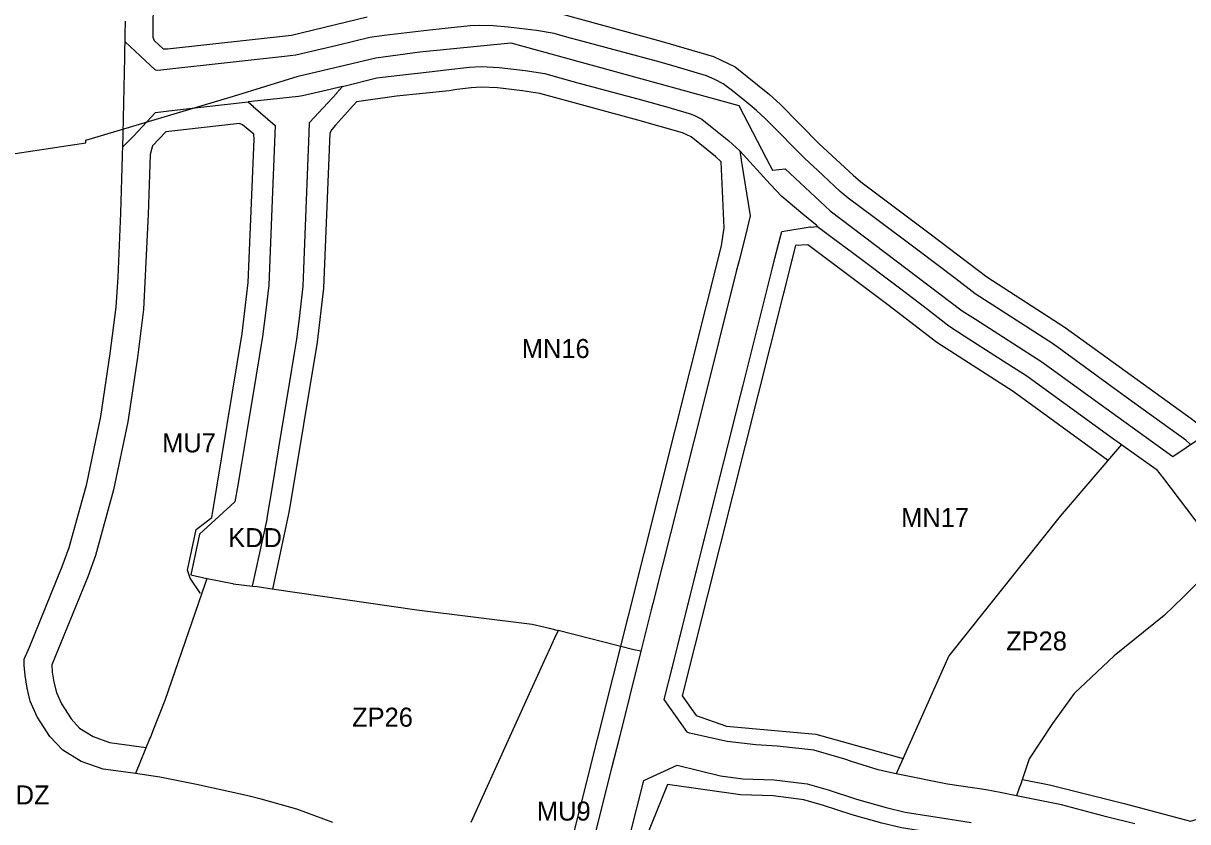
# Model space of a CAD drawing. Extents: x 7428103 to 7431580, y 5545880 to 5549002.
# Drawn here: x 7430217.3 to 7430556.7, y 5547582.8 to 5547815.6 of the extents above; entities that cross this region are included whole.
import ezdxf

# ---------------------------------------------------------------- set-up
doc = ezdxf.new("R2010")
doc.units = 0
for name, color, linetype in [('CZ_L_linie rozgraniczające tereny o różnym przeznaczeniu oraz różnych warunkach ich zabudowy i zagospodarowania', 7, 'Continuous'), ('CZ_L_maksymalne nieprzekraczalne linie zabudowy', 7, 'Continuous'), ('CZ_L_opisy_linie rozgraniczające tereny o różnym przeznaczeniu oraz różnych warunkach ich zabudowy i zagospodarowania', 7, 'Continuous'), ('Łąki_Nowohuckie', 7, 'Continuous')]:
    doc.layers.add(name, color=color, linetype=linetype)

msp = doc.modelspace()

# ---------------------------------------------------------------- linework, layer by layer
at = {"layer": 'CZ_L_linie rozgraniczające tereny o różnym przeznaczeniu oraz różnych warunkach ich zabudowy i zagospodarowania'}
for p, q in [((7430247, 5547812.36), (7430247.08, 5547816.27)), ((7430334.03, 5547813.4), (7430322.49, 5547812.07)), ((7430341.14, 5547814.21), (7430334.03, 5547813.4)), ((7430347.51, 5547814.87), (7430341.14, 5547814.21)), ((7430350.39, 5547815.02), (7430347.51, 5547814.87)), ((7430354.22, 5547814.91), (7430350.39, 5547815.02)), ((7430358.61, 5547814.55), (7430354.22, 5547814.91)), ((7430366.92, 5547813.53), (7430358.61, 5547814.55)), ((7430372.07, 5547812.71), (7430366.92, 5547813.53)), ((7430375.37, 5547811.73), (7430372.07, 5547812.71)), ((7430246.91, 5547807.98), (7430246.95, 5547810.2)), ((7430246.95, 5547810.2), (7430247, 5547812.36)), ((7430251.35, 5547806.18), (7430246.95, 5547810.2)), ((7430318.27, 5547811.53), (7430308.81, 5547809.19)), ((7430322.49, 5547812.07), (7430318.27, 5547811.53)), ((7430380.49, 5547810.32), (7430375.37, 5547811.73)), ((7430390.95, 5547807.51), (7430380.49, 5547810.32)), ((7430246.86, 5547805.74), (7430246.91, 5547807.98)), ((7430255.84, 5547802.01), (7430251.35, 5547806.18)), ((7430293.44, 5547805.94), (7430279.35, 5547804.37)), ((7430296.73, 5547806.32), (7430293.44, 5547805.94)), ((7430308.81, 5547809.19), (7430296.73, 5547806.32)), ((7430401.9, 5547804.57), (7430390.95, 5547807.51)), ((7430246.36, 5547783.41), (7430246.86, 5547805.74)), ((7430279.35, 5547804.37), (7430256.5, 5547801.84)), ((7430340.44, 5547802.05), (7430347.34, 5547802.8)), ((7430347.34, 5547802.8), (7430350.73, 5547803.01)), ((7430350.73, 5547803.01), (7430355.97, 5547802.78)), ((7430355.97, 5547802.78), (7430363.61, 5547801.89)), ((7430407, 5547803.12), (7430401.9, 5547804.57)), ((7430412.88, 5547801.41), (7430407, 5547803.12)), ((7430256.5, 5547801.84), (7430255.84, 5547802.01)), ((7430310.33, 5547797.22), (7430320.37, 5547799.69)), ((7430320.37, 5547799.69), (7430321.98, 5547799.93)), ((7430321.98, 5547799.93), (7430327, 5547800.51)), ((7430327, 5547800.51), (7430336.43, 5547801.59)), ((7430336.43, 5547801.59), (7430340.44, 5547802.05)), ((7430363.61, 5547801.89), (7430369.32, 5547801)), ((7430369.32, 5547801), (7430373.04, 5547799.9)), ((7430373.04, 5547799.9), (7430378.89, 5547798.32)), ((7430416.45, 5547800.32), (7430412.88, 5547801.41)), ((7430418.83, 5547799.21), (7430416.45, 5547800.32)), ((7430421.31, 5547798.01), (7430418.83, 5547799.21)), ((7430306.72, 5547796.36), (7430298.69, 5547794.47)), ((7430310.33, 5547797.22), (7430306.72, 5547796.36)), ((7430308.6, 5547795.27), (7430310.33, 5547797.22)), ((7430378.89, 5547798.32), (7430389.78, 5547795.4)), ((7430423.98, 5547795.93), (7430421.31, 5547798.01)), ((7430429.17, 5547791.75), (7430423.98, 5547795.93)), ((7430269.91, 5547791.25), (7430282.86, 5547792.69)), ((7430289.35, 5547793.41), (7430282.86, 5547792.69)), ((7430282.86, 5547792.69), (7430284.34, 5547791.35)), ((7430297.46, 5547794.32), (7430289.35, 5547793.41)), ((7430298.69, 5547794.47), (7430297.46, 5547794.32)), ((7430300.75, 5547786.71), (7430308.65, 5547795.28)), ((7430308.65, 5547795.28), (7430308.6, 5547795.27)), ((7430389.78, 5547795.4), (7430396.41, 5547793.62)), ((7430396.41, 5547793.62), (7430405.15, 5547791.16)), ((7430249.37, 5547782.72), (7430255.8, 5547789.6)), ((7430255.8, 5547789.6), (7430259.69, 5547790.11)), ((7430259.69, 5547790.11), (7430269.91, 5547791.25)), ((7430284.34, 5547791.35), (7430284.29, 5547791.34)), ((7430284.29, 5547791.34), (7430290.72, 5547785.81)), ((7430405.15, 5547791.16), (7430411.38, 5547789.35)), ((7430411.38, 5547789.35), (7430412.73, 5547788.81)), ((7430431.05, 5547790.24), (7430429.17, 5547791.75)), ((7430433.66, 5547787.78), (7430431.05, 5547790.24)), ((7430290.72, 5547785.81), (7430289.66, 5547759.2)), ((7430300.64, 5547783.67), (7430300.75, 5547786.71)), ((7430412.73, 5547788.81), (7430415.06, 5547787.7)), ((7430415.06, 5547787.7), (7430418.12, 5547785.24)), ((7430436.96, 5547784.44), (7430433.66, 5547787.78)), ((7430246.28, 5547779.62), (7430246.36, 5547783.41)), ((7430246.28, 5547779.62), (7430249.37, 5547782.72)), ((7430299.85, 5547763.91), (7430300.64, 5547783.67)), ((7430418.12, 5547785.24), (7430422.92, 5547781.38)), ((7430442.56, 5547778.77), (7430436.96, 5547784.44)), ((7430246.23, 5547777.58), (7430246.28, 5547779.62)), ((7430422.92, 5547781.38), (7430426.12, 5547778.41)), ((7430445.14, 5547776.19), (7430442.56, 5547778.77)), ((7430245.68, 5547760.22), (7430246.22, 5547777.02)), ((7430246.22, 5547777.02), (7430246.23, 5547777.58)), ((7430435, 5547768.74), (7430426.12, 5547778.41)), ((7430426.12, 5547778.41), (7430426.57, 5547775.78)), ((7430426.57, 5547775.78), (7430426.6, 5547775.74)), ((7430426.6, 5547775.74), (7430429.22, 5547759.52)), ((7430448.8, 5547772.78), (7430445.14, 5547776.19)), ((7430455.42, 5547766.6), (7430448.8, 5547772.78)), ((7430438.4, 5547765.1), (7430435, 5547768.74)), ((7430444.5, 5547760), (7430438.4, 5547765.1)), ((7430457.79, 5547764.62), (7430455.42, 5547766.6)), ((7430298.96, 5547741.46), (7430299.85, 5547763.91)), ((7430465.3, 5547759), (7430457.79, 5547764.62)), ((7430244.88, 5547741.63), (7430245.68, 5547760.22)), ((7430289.66, 5547759.2), (7430288.82, 5547739.24)), ((7430429.22, 5547759.52), (7430427.68, 5547753.39)), ((7430448.66, 5547756.53), (7430444.5, 5547760)), ((7430478.06, 5547749.46), (7430465.3, 5547759)), ((7430437.91, 5547753.06), (7430438.37, 5547754.91)), ((7430438.37, 5547754.91), (7430446.66, 5547756.25)), ((7430446.66, 5547756.25), (7430446.75, 5547756.18)), ((7430446.75, 5547756.18), (7430448.66, 5547756.39)), ((7430448.66, 5547756.39), (7430448.66, 5547756.53)), ((7430448.66, 5547756.39), (7430448.82, 5547756.4)), ((7430448.82, 5547756.4), (7430452.31, 5547753.71)), ((7430427.68, 5547753.39), (7430425.94, 5547746.46)), ((7430436.41, 5547747.1), (7430437.91, 5547753.06)), ((7430452.31, 5547753.71), (7430453.45, 5547752.88)), ((7430453.45, 5547752.88), (7430459.36, 5547748.46)), ((7430459.36, 5547748.46), (7430472.67, 5547738.51)), ((7430489.09, 5547741.07), (7430478.06, 5547749.46)), ((7430425.94, 5547746.46), (7430425.14, 5547743.28)), ((7430435.62, 5547743.93), (7430436.41, 5547747.1)), ((7430244.37, 5547732.88), (7430244.88, 5547741.63)), ((7430298.85, 5547738.93), (7430298.96, 5547741.46)), ((7430425.14, 5547743.28), (7430415.05, 5547703)), ((7430427.12, 5547710.07), (7430435.62, 5547743.93)), ((7430288.82, 5547739.24), (7430287.98, 5547732.02)), ((7430297.75, 5547729.5), (7430298.85, 5547738.93)), ((7430472.67, 5547738.51), (7430480.84, 5547732.28)), ((7430494.74, 5547736.72), (7430489.09, 5547741.07)), ((7430503.96, 5547730.83), (7430494.74, 5547736.72)), ((7430242.63, 5547719.31), (7430244.37, 5547732.88)), ((7430287.95, 5547731.83), (7430287.04, 5547724.29)), ((7430287.98, 5547732.02), (7430287.93, 5547731.99)), ((7430287.93, 5547731.99), (7430287.95, 5547731.83)), ((7430480.84, 5547732.28), (7430487.1, 5547727.45)), ((7430297.05, 5547723.52), (7430297.75, 5547729.5)), ((7430508.12, 5547728.17), (7430503.96, 5547730.83)), ((7430517.58, 5547722.04), (7430508.12, 5547728.17)), ((7430487.1, 5547727.45), (7430491.55, 5547724.52)), ((7430491.55, 5547724.52), (7430502.97, 5547717.22)), ((7430287.04, 5547724.29), (7430285.17, 5547713.04)), ((7430296.47, 5547720.03), (7430297.05, 5547723.52)), ((7430533.18, 5547710.67), (7430517.58, 5547722.04)), ((7430239.87, 5547700.97), (7430242.63, 5547719.31)), ((7430294.79, 5547709.91), (7430296.47, 5547720.03)), ((7430502.97, 5547717.22), (7430509.82, 5547712.84)), ((7430285.16, 5547713), (7430282.44, 5547696.59)), ((7430285.19, 5547713.02), (7430285.16, 5547713)), ((7430285.17, 5547713.04), (7430285.19, 5547713.02)), ((7430509.82, 5547712.84), (7430515.61, 5547708.63)), ((7430292.38, 5547695.43), (7430294.79, 5547709.91)), ((7430426.37, 5547707.08), (7430427.12, 5547710.07)), ((7430515.61, 5547708.63), (7430526.51, 5547700.69)), ((7430540.66, 5547705.22), (7430533.18, 5547710.67)), ((7430416.66, 5547668.44), (7430426.37, 5547707.08)), ((7430554.16, 5547695.55), (7430540.66, 5547705.22)), ((7430235.8, 5547681.29), (7430239.87, 5547700.97)), ((7430415.05, 5547703), (7430403.62, 5547657.57)), ((7430526.51, 5547700.69), (7430534.45, 5547694.9)), ((7430282.44, 5547696.59), (7430280.89, 5547687.23)), ((7430290.08, 5547681.57), (7430292.38, 5547695.43)), ((7430534.45, 5547694.9), (7430537.42, 5547692.77)), ((7430556.18, 5547694.04), (7430554.16, 5547695.55)), ((7430557.44, 5547692.86), (7430556.18, 5547694.04)), ((7430537.42, 5547692.77), (7430519.55, 5547671.91)), ((7430537.42, 5547692.77), (7430547.49, 5547685.56)), ((7430280.89, 5547687.23), (7430279.85, 5547680.96)), ((7430547.49, 5547685.56), (7430549.72, 5547682.85)), ((7430230.6, 5547662.74), (7430235.8, 5547681.29)), ((7430279.85, 5547680.96), (7430278.97, 5547676.11)), ((7430288.39, 5547671.35), (7430290.08, 5547681.57)), ((7430549.72, 5547682.85), (7430560.99, 5547667.96)), ((7430278.97, 5547676.11), (7430268.6, 5547666.6)), ((7430284.13, 5547651.51), (7430288.32, 5547670.94)), ((7430288.32, 5547670.94), (7430288.39, 5547671.35)), ((7430519.55, 5547671.91), (7430487.09, 5547631.17)), ((7430413.27, 5547654.91), (7430416.66, 5547668.44)), ((7430268.6, 5547666.6), (7430266.12, 5547654.83)), ((7430228.65, 5547657.24), (7430230.6, 5547662.74)), ((7430219.05, 5547633.73), (7430228.65, 5547657.24)), ((7430403.62, 5547657.57), (7430400.83, 5547646.44)), ((7430266.12, 5547654.83), (7430270.81, 5547653.74)), ((7430270.81, 5547653.74), (7430270.32, 5547652.24)), ((7430270.81, 5547653.74), (7430270.84, 5547653.73)), ((7430270.84, 5547653.73), (7430274.38, 5547653.02)), ((7430406.49, 5547627.94), (7430413.27, 5547654.91)), ((7430270.32, 5547652.24), (7430258.56, 5547618.15)), ((7430274.38, 5547653.02), (7430275.39, 5547652.81)), ((7430275.39, 5547652.81), (7430278.31, 5547652.22)), ((7430278.31, 5547652.22), (7430278.37, 5547652.21)), ((7430278.37, 5547652.21), (7430278.41, 5547652.2)), ((7430278.41, 5547652.2), (7430284.13, 5547651.51)), ((7430284.13, 5547651.51), (7430285.45, 5547651.35)), ((7430285.45, 5547651.35), (7430290.4, 5547650.61)), ((7430290.4, 5547650.61), (7430331.98, 5547644.56)), ((7430400.83, 5547646.44), (7430400.35, 5547644.55)), ((7430331.98, 5547644.56), (7430365.59, 5547640.4)), ((7430400.35, 5547644.55), (7430397.33, 5547632.51)), ((7430365.59, 5547640.4), (7430369.02, 5547639.57)), ((7430369.02, 5547639.57), (7430370.58, 5547639.22)), ((7430370.58, 5547639.22), (7430373.19, 5547638.56)), ((7430372.17, 5547636.31), (7430370.87, 5547633.46)), ((7430373.19, 5547638.56), (7430372.17, 5547636.31)), ((7430395.27, 5547632.88), (7430373.19, 5547638.56)), ((7430217.57, 5547630.23), (7430219.05, 5547633.73)), ((7430370.87, 5547633.46), (7430369.65, 5547630.78)), ((7430397.33, 5547632.51), (7430395.27, 5547632.88)), ((7430217.54, 5547628.39), (7430217.57, 5547630.23)), ((7430369.65, 5547630.78), (7430364.28, 5547618.97)), ((7430397.33, 5547632.51), (7430393.98, 5547619.16)), ((7430487.09, 5547631.17), (7430471.73, 5547596.75)), ((7430217.78, 5547625.41), (7430217.54, 5547628.39)), ((7430404.11, 5547618.45), (7430406.49, 5547627.94)), ((7430218.39, 5547621.75), (7430217.78, 5547625.41)), ((7430219.29, 5547617.95), (7430218.39, 5547621.75)), ((7430393.98, 5547619.16), (7430390.84, 5547606.66)), ((7430221.36, 5547613.33), (7430219.29, 5547617.95)), ((7430258.56, 5547618.15), (7430255.06, 5547609.26)), ((7430364.28, 5547618.97), (7430355.34, 5547599.3)), ((7430410.71, 5547609.06), (7430404.11, 5547618.45)), ((7430224.96, 5547607.68), (7430221.36, 5547613.33)), ((7430255.06, 5547609.26), (7430254.65, 5547608.25)), ((7430410.85, 5547608.87), (7430410.71, 5547609.06)), ((7430228.76, 5547603.66), (7430224.96, 5547607.68)), ((7430254.2, 5547607.14), (7430249.99, 5547596.81)), ((7430254.42, 5547607.68), (7430254.2, 5547607.14)), ((7430254.65, 5547608.25), (7430254.42, 5547607.68)), ((7430390.84, 5547606.66), (7430388.75, 5547598.35)), ((7430411.52, 5547608.64), (7430410.85, 5547608.87)), ((7430422.47, 5547606.13), (7430411.52, 5547608.64)), ((7430430.83, 5547605.22), (7430422.47, 5547606.13)), ((7430234.14, 5547600.38), (7430228.76, 5547603.66)), ((7430437.03, 5547604.79), (7430430.83, 5547605.22)), ((7430445.12, 5547603.95), (7430437.03, 5547604.79)), ((7430447.74, 5547603.65), (7430445.12, 5547603.95)), ((7430454.49, 5547601.7), (7430447.74, 5547603.65)), ((7430240.56, 5547598.06), (7430234.14, 5547600.38)), ((7430355.34, 5547599.3), (7430347.7, 5547582.51)), ((7430398.17, 5547594.79), (7430407.93, 5547599.3)), ((7430407.93, 5547599.3), (7430420.48, 5547596.2)), ((7430456.81, 5547600.98), (7430454.49, 5547601.7)), ((7430458.69, 5547600.39), (7430456.81, 5547600.98)), ((7430466.49, 5547597.91), (7430458.69, 5547600.39)), ((7430247.21, 5547597.21), (7430240.56, 5547598.06)), ((7430249.99, 5547596.81), (7430247.21, 5547597.21)), ((7430257.06, 5547595.78), (7430249.99, 5547596.81)), ((7430267.77, 5547593.6), (7430257.06, 5547595.78)), ((7430388.75, 5547598.35), (7430381.91, 5547571.1)), ((7430420.48, 5547596.2), (7430427, 5547595.25)), ((7430468.99, 5547597.3), (7430466.49, 5547597.91)), ((7430471.73, 5547596.75), (7430468.99, 5547597.3)), ((7430486.75, 5547593.73), (7430471.73, 5547596.75)), ((7430282.31, 5547590.47), (7430267.77, 5547593.6)), ((7430394.32, 5547579.46), (7430398.17, 5547594.79)), ((7430427, 5547595.25), (7430436.18, 5547594.97)), ((7430436.18, 5547594.97), (7430441.77, 5547594.36)), ((7430441.77, 5547594.36), (7430445.77, 5547593.81)), ((7430445.77, 5547593.81), (7430451.94, 5547592.03)), ((7430451.94, 5547592.03), (7430460.16, 5547589.32)), ((7430497.98, 5547592.05), (7430486.75, 5547593.73)), ((7430502.09, 5547591.31), (7430497.98, 5547592.05)), ((7430286.62, 5547589.32), (7430282.31, 5547590.47)), ((7430296.98, 5547586.48), (7430286.62, 5547589.32)), ((7430460.16, 5547589.32), (7430468.79, 5547586.93)), ((7430506.85, 5547590.36), (7430502.09, 5547591.31)), ((7430519.96, 5547587.75), (7430506.85, 5547590.36)), ((7430307.53, 5547582.53), (7430296.98, 5547586.48)), ((7430468.79, 5547586.93), (7430474.35, 5547585.61)), ((7430474.35, 5547585.61), (7430489.32, 5547583.23)), ((7430524.29, 5547586.53), (7430519.96, 5547587.75)), ((7430533.09, 5547584.22), (7430524.29, 5547586.53)), ((7430489.32, 5547583.23), (7430493.65, 5547582.59)), ((7430541.3, 5547582.12), (7430533.09, 5547584.22))]:
    msp.add_line(p, q, dxfattribs=at)
for points in [[(7430566.79, 5547659.49), (7430565.68, 5547658.44), (7430565.66, 5547658.48), (7430563.17, 5547655.93), (7430555.54, 5547648.41), (7430549.91, 5547642.91), (7430535.33, 5547631.2), (7430523.61, 5547620.18), (7430517.27, 5547611.44), (7430510.47, 5547601.09), (7430507.89, 5547593.24), (7430507.83, 5547593.26), (7430507.8, 5547593.17), (7430506.85, 5547590.37)], [(7430506.85, 5547590.37), (7430506.85, 5547590.36)]]:
    msp.add_lwpolyline(points, dxfattribs=at)
at = {"layer": 'CZ_L_maksymalne nieprzekraczalne linie zabudowy'}
for points in [[(7430255.21, 5547836.54), (7430254.99, 5547811.64), (7430255.43, 5547810.59), (7430258.03, 5547808.17), (7430259.27, 5547808.18), (7430295.46, 5547812.22), (7430317.51, 5547817.49)], [(7430373.39, 5547818.56), (7430403.54, 5547810.34), (7430418.52, 5547805.95), (7430424.77, 5547802.91), (7430434.82, 5547794.91), (7430437.91, 5547792.01), (7430449.28, 5547780.53), (7430459.17, 5547771.31), (7430461.45, 5547769.38), (7430481.66, 5547754.26), (7430498.13, 5547741.68), (7430521.04, 5547726.94), (7430557.73, 5547700.37), (7430560.25, 5547698.45), (7430562.39, 5547696.25)], [(7430371.2, 5547553.08), (7430420.8, 5547750.74), (7430421.64, 5547756.01), (7430420.68, 5547775.27), (7430419.07, 5547776.77), (7430411.96, 5547782.49), (7430409.49, 5547783.65), (7430396.41, 5547787.39), (7430367.88, 5547795.16), (7430362.79, 5547795.95), (7430355.5, 5547796.79), (7430350.78, 5547797), (7430347.85, 5547796.82), (7430343.63, 5547796.37), (7430341.44, 5547795.97), (7430326.04, 5547794.35), (7430314.38, 5547792.75), (7430308.3, 5547785.97), (7430307.22, 5547784.65), (7430306.64, 5547783.64), (7430304.82, 5547738.37), (7430302.98, 5547722.62), (7430295.02, 5547674.59), (7430294.56, 5547672.6), (7430289.92, 5547650.62)], [(7430268.91, 5547649.31), (7430265.93, 5547653.81), (7430265.11, 5547656.13), (7430267.64, 5547668.04), (7430272.22, 5547671.55), (7430281.1, 5547725.15), (7430282.85, 5547740.09), (7430284.55, 5547781.79), (7430284.48, 5547783.27), (7430281.22, 5547786.07), (7430280.29, 5547786.37), (7430258.8, 5547783.94), (7430254.94, 5547779.88), (7430254.23, 5547777.33), (7430253.68, 5547759.88), (7430252.33, 5547732.15), (7430250.54, 5547718.14), (7430247.71, 5547699.37), (7430243.6, 5547679.54), (7430238.28, 5547660.47), (7430236.06, 5547654.22), (7430225.55, 5547628.52), (7430225.72, 5547626.43), (7430226.22, 5547623.46), (7430226.94, 5547620.44), (7430228.42, 5547617.13), (7430231.22, 5547612.75), (7430233.69, 5547610.08), (7430237.68, 5547607.6), (7430242.38, 5547605.91), (7430253.09, 5547604.44)], [(7430533.38, 5547688.26), (7430505.87, 5547708.25), (7430483.64, 5547722.54), (7430469.31, 5547733.52), (7430445.97, 5547751.02), (7430442.35, 5547750.8), (7430409.4, 5547619.45), (7430413.44, 5547613.71), (7430422.29, 5547610.65), (7430448.28, 5547608.32), (7430473.78, 5547601.25)], [(7430508.56, 5547595.12), (7430516.4, 5547593.55), (7430538.25, 5547588.06), (7430557.51, 5547582.97), (7430564.09, 5547584.92), (7430569.35, 5547590.07), (7430584.45, 5547607.15), (7430562.9, 5547655.66)], [(7430495.47, 5547577.51), (7430473.26, 5547581.04), (7430467.54, 5547582.4), (7430458.91, 5547584.79), (7430450.54, 5547587.54), (7430444.79, 5547589.2), (7430435.85, 5547590.28), (7430426.33, 5547590.6), (7430405.05, 5547593.59), (7430398.88, 5547578.32), (7430390.21, 5547543.77), (7430391.83, 5547539.65), (7430409.68, 5547528.84), (7430488.29, 5547479.07), (7430489.28, 5547479.21), (7430483.39, 5547520.62), (7430484.01, 5547534.06), (7430485.45, 5547544.72), (7430495.24, 5547577.37)]]:
    msp.add_lwpolyline(points, dxfattribs=at)
at = {"layer": 'Łąki_Nowohuckie'}
for p, q in [((7430278.55, 5547794.37), (7430297.45, 5547800.26)), ((7430235.48, 5547781.59), (7430278.55, 5547794.37)), ((7430214.92, 5547777.68), (7430235.46, 5547780.82)), ((7430235.46, 5547780.82), (7430235.48, 5547781.59)), ((7430439.42, 5547773.17), (7430452.54, 5547760.91)), ((7430452.54, 5547760.91), (7430491.02, 5547731.81)), ((7430491.02, 5547731.81), (7430494.88, 5547729.34)), ((7430494.88, 5547729.34), (7430514.2, 5547716.94)), ((7430514.2, 5547716.94), (7430530.42, 5547705.11)), ((7430530.42, 5547705.11), (7430552.35, 5547689.31)), ((7430552.35, 5547689.31), (7430568.02, 5547699.89))]:
    msp.add_line(p, q, dxfattribs=at)
for points in [[(7430297.45, 5547800.26), (7430320.09, 5547805.53), (7430332.9, 5547807.33), (7430359.44, 5547809.97), (7430425.9, 5547791.62), (7430433.88, 5547776.29)], [(7430433.88, 5547776.29), (7430434.95, 5547774.23), (7430435.66, 5547772.85), (7430439.42, 5547773.17)]]:
    msp.add_lwpolyline(points, dxfattribs=at)

# ---------------------------------------------------------------- texts
at = {"layer": 'CZ_L_opisy_linie rozgraniczające tereny o różnym przeznaczeniu oraz różnych warunkach ich zabudowy i zagospodarowania'}
for s, p in [('MN16', (7430362.59, 5547718.02)), ('MU7', (7430257.73, 5547690.5)), ('MN17', (7430473.19, 5547668.74)), ('KDD', (7430277, 5547662.86)), ('ZP28', (7430503.78, 5547632.72)), ('ZP26', (7430313.12, 5547610.5)), ('KDZ', (7430210.09, 5547587.82)), ('MU9', (7430367.01, 5547583.11))]:
    msp.add_text(s, height=5.549, dxfattribs=at).set_placement(p)

doc.saveas('drawing.dxf')
